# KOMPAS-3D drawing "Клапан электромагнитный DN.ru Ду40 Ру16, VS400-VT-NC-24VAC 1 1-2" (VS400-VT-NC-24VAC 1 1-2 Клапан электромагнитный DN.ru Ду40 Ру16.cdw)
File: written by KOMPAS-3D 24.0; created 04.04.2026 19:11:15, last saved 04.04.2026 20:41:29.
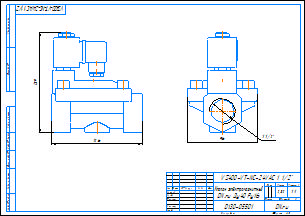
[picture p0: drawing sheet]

Document properties: c3d_UniqueCompID: ef56311e-7521-43dc-8291-0e6108b3d81d; Обозначение: VS400-ET-NC-220VAC 1; Наименование: Клапан электромагнитный DN.ru Ду25 Ру16; Автор: artio; Класс точности: c; Знак неуказанной шероховатости: Шероховатость не задана; Рассекать на разрезах: Да; c3d_UniqueCompID: ef56311e-7521-43dc-8291-0e6108b3d81d; Обозначение: VS400-ET-NC-220VAC 1-2; Наименование: Клапан электромагнитный DN.ru Ду15 Ру16; Автор: artio; Класс точности: c; Знак неуказанной шероховатости: Шероховатость не задана; Рассекать на разрезах: Да; c3d_UniqueCompID: ef56311e-7521-43dc-8291-0e6108b3d81d; Обозначение: VS400-ET-NC-220VAC 3-4; Наименование: Клапан электромагнитный DN.ru Ду20 Ру16; Автор: artio; Класс точности: c; Знак неуказанной шероховатости: Шероховатость не задана; Рассекать на разрезах: Да; c3d_UniqueCompID: ef56311e-7521-43dc-8291-0e6108b3d81d; Обозначение: VS400-ET-NC-220VAC 1 1-4; Наименование: Клапан электромагнитный DN.ru Ду32 Ру16; Автор: artio; Класс точности: c; Знак неуказанной шероховатости: Шероховатость не задана; Рассекать на разрезах: Да; c3d_UniqueCompID: ef56311e-7521-43dc-8291-0e6108b3d81d; Обозначение: VS400-ET-NC-220VAC 3-8; Наименование: Клапан электромагнитный DN.ru Ду10 Ру16; Автор: artio; Класс точности: c; Знак неуказанной шероховатости: Шероховатость не задана; Рассекать на разрезах: Да; c3d_UniqueCompID: ef56311e-7521-43dc-8291-0e6108b3d81d; Обозначение: VS400-ET-NC-220VAC 1 1-2; Наименование: Клапан электромагнитный DN.ru Ду40 Ру16; Автор: artio; Класс точности: c; Знак неуказанной шероховатости: Шероховатость не задана; Рассекать на разрезах: Да; Автор: artio; Форматы листов документа: A3; Полное имя файла: VS400-VT-NC-24VAC 1 1-2 Клапан электромагнитный DN.ru Ду40 Ру16.m3d; Масса: 2.321; Наименование: Клапан электромагнитный DN.ru Ду40 Ру16; Количество листов документа: 1; Примечание: D130-05501

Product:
- Body: Тело 1  | qty 1
    Масса: 4.144257
- Part/product: Клапан электромагнитный DN.ru Ду40 Ру16  | designation VS400-VT-NC-24VAC 1 1-2
    Масса: 2.321
    Раздел спецификации: Прочие изделия
    Примечание: D130-05501
    additional columns: ef56311e-7521-43dc-8291-0e6108b3d81d; VS400-ET-NC-220VAC 1 1-2; artio; c; Шероховатость не задана; Да

Views: Вид 1, Спереди
Referenced files in C:\Users\artio\OneDrive\Рабочий стол\Клапан электромагнитный DN.ru\VS400-ET-NC\VS400-ET-NC-24VDC\: VS400-ET-NC-24VDC 3-8 Клапан электромагнитный DN.ru Ду10 Ру16.m3d
Referenced files in C:\Users\artio\OneDrive\Рабочий стол\Клапан электромагнитный DN.ru\VS400-VT-NC\VS400-VT-NC-24VAC\: VS400-VT-NC-24VAC 1 1-2 Клапан электромагнитный DN.ru Ду40 Ру16.m3d
Referenced files in C:\Users\artio\OneDrive\Рабочий стол\Клапан электромагнитный DN.ru\VS400-ET-NC\: VS400-ET-NC-24VDC 3-8 Клапан электромагнитный DN.ru Ду10 Ру16.cdw
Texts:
  VS400-VT-NC-24VAC 1 1-2
  Клапан электромагнитный
  DN.ru Ду40 Ру16
  VS400-VT-NC-24VAC 1 1/2"
  VS400-VT-NC-24VAC 1 1/2"-
  Клапан электромагнитный DN.ru Ду40 Ру16
  VS400-VT-NC-24VAC 1 1-2 Клапан электромагнитный DN.ru Ду40 Ру16
Dimensions and other numbers on the sheet: 0; 3; 2; 4; 96; 1 1/2"; 1:1; 1; 2,32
